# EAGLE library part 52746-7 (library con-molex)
FPC Connector ZIF for SMT 0.5mm Source: http://www.farnell.com/datasheets/73044.pdf [DWG. NO. (Sheet 1 OF 2) SD-52746-**17]
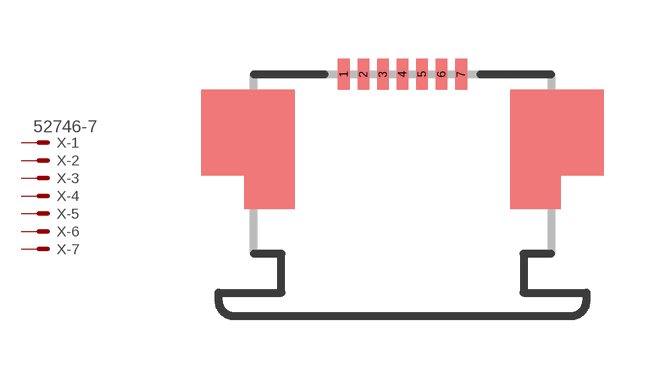
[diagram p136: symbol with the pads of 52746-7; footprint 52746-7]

Designator prefix X; gates -1=MV -2=M -3=M -4=M -5=M -6=M -7=M

## 52746-7 (OC_FARNELL: unknown; OC_NEWARK: unknown)  [52746-7]
1  -1:S  pas
2  -2:S  pas
3  -3:S  pas
4  -4:S  pas
5  -5:S  pas
6  -6:S  pas
7  -7:S  pas

## Footprint 52746-7 (pad centres in mm)
FPC Connector ZIF for SMT 0.5mm Source: http://www.farnell.com/datasheets/73044.pdf [DWG. NO. (Sheet 1 OF 2) SD-52746-**17]
smd 0.3 x 0.8: 1 -1.5,0.6; 2 -1,0.6; 3 -0.5,0.6; 4 0,0.6; 5 0.5,0.6; 6 1,0.6; 7 1.5,0.6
